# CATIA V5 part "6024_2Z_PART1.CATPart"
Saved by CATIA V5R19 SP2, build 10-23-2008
Part number: 6024_2Z_PART1
Bounding box of the stored display mesh (mm): x 0 to 28, y -69.409 to 69.409, z -69.481 to 69.481
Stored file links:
  G:\EU_thinkMotion\CFAO_2010\MMS_groupe2\MMS_groupe2\OK\nrosalie\nrosalie_cfao_support_d_arme_legere_final\6024_2Z_PART1.CATPart
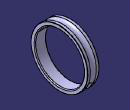
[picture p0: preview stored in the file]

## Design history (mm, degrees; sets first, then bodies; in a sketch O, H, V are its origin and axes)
Set1
  Point1: (0, 0, 0)
  Point2: (1, 0, 0)
  Point3: (0, 1, 0)
  Plane1: type 3Points, Element1 Point1, Element2 Point2, Element3 Point3
Body1 (main body)
  Sketch1 on Plane1, origin (0, 0, 0), H (1, 0, 0), V (0, 1, 0)
    arc A1 centre (2, 62) radius 2 from (0, 62) to (2, 60) ccw
    point P1 (2, 60)
    point P2 (26, 60)
    line L1 (2, 60) -> (26, 60)
    arc A2 centre (26, 62) radius 2 from (26, 60) to (28, 62) ccw
    point P3 (28, 62)
    point P4 (28, 68.833)
    line L2 (28, 62) -> (28, 68.833)
    arc A3 centre (27.333, 68.833) radius 0.667 from (28, 68.833) to (27.333, 69.5) ccw
    point P5 (27.333, 69.5)
    point P6 (21.2849, 69.5)
    line L3 (27.333, 69.5) -> (21.2849, 69.5)
    arc A4 centre (14, 75) radius 9.128 from (6.7151, 69.5) to (21.2849, 69.5) ccw
    point P7 (6.7151, 69.5)
    point P8 (0.667, 69.5)
    line L4 (6.7151, 69.5) -> (0.667, 69.5)
    arc A5 centre (0.667, 68.833) radius 0.667 from (0.667, 69.5) to (0, 68.833) ccw
    point P9 (0, 68.833)
    point P10 (0, 62)
    line L5 (0, 68.833) -> (0, 62)
    point P11 (26, 0)
    point P12 (2, 0)
    axis line L6 (26, 0) -> (2, 0)
    point P13 (0, 62)
    point P14 (2, 60)
    point P15 (2, 60)
    point P16 (26, 60)
    point P17 (26, 60)
    point P18 (28, 62)
    point P19 (28, 62)
    point P20 (28, 68.833)
    point P21 (28, 68.833)
    point P22 (27.333, 69.5)
    point P23 (27.333, 69.5)
    point P24 (21.2849, 69.5)
    point P25 (6.7151, 69.5)
    point P26 (21.2849, 69.5)
    point P27 (6.7151, 69.5)
    point P28 (0.667, 69.5)
    point P29 (0.667, 69.5)
    point P30 (0, 68.833)
    point P31 (0, 68.833)
    point P32 (0, 62)
    coincidence: P13 P32, P14 P15, P16 P17, P18 P19, P20 P21, P22 P23, P24 P26, P25 P27, P28 P29, P30 P31
  Shaft1: profile Sketch1, axis Sketch1.L6, angle 360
